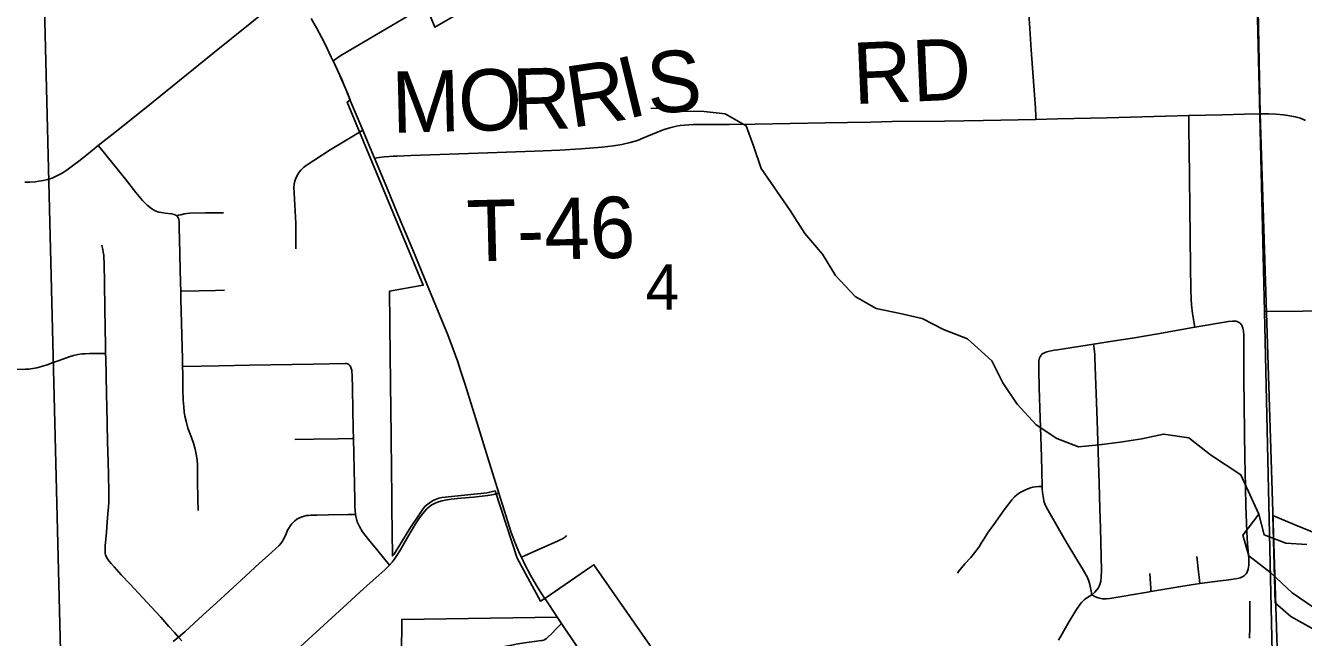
# Model space of a CAD drawing. Extents: x -6.4 to 34, y -4.2 to 22.
# Drawn here: x 5.93 to 7.115, y 14.854 to 15.421 of the extents above; entities that cross this region are included whole.
import ezdxf

# ---------------------------------------------------------------- set-up
doc = ezdxf.new("R2010")
doc.units = 0
for name, color, linetype in [('GM_X_City_Street', 7, 'Continuous'), ('GM_X_Corporation', 7, 'Continuous'), ('GM_X_County_Road', 7, 'Continuous'), ('GM_X_Major_Lake', 7, 'Continuous'), ('GM_X_Minor_River', 7, 'Continuous'), ('GM_X_Section_Text', 7, 'Continuous'), ('GM_X_Township_Road', 7, 'Continuous'), ('GM_X_Township_Road_Text', 7, 'Continuous'), ('GM_X_US_Route', 7, 'Continuous')]:
    doc.layers.add(name, color=color, linetype=linetype)

msp = doc.modelspace()

# ---------------------------------------------------------------- linework, layer by layer
at = {"layer": 'GM_X_City_Street'}
for points in [[(6.1803, 15.214), (6.1803, 15.2376), (6.1787, 15.271), (6.1788, 15.2734), (6.1792, 15.2757), (6.1802, 15.2785), (6.1817, 15.2818), (6.1835, 15.2849), (6.1854, 15.2872), (6.1875, 15.2893), (6.1899, 15.2911), (6.2123, 15.3055), (6.2292, 15.3158), (6.2424, 15.3238)], [(6.0898, 14.9715), (6.0896, 14.9821), (6.0894, 14.9991), (6.0893, 15.0075), (6.0891, 15.0138), (6.0888, 15.0183), (6.0881, 15.0238), (6.0872, 15.0284), (6.0855, 15.0338), (6.0836, 15.039), (6.0804, 15.0478), (6.0786, 15.0542), (6.0776, 15.0588), (6.0769, 15.0628), (6.0765, 15.0676), (6.0761, 15.0737), (6.0758, 15.0835), (6.0755, 15.098), (6.0754, 15.1048), (6.0752, 15.1116), (6.0738, 15.1677), (6.0737, 15.1748), (6.0735, 15.1824), (6.0729, 15.2079), (6.0726, 15.2237), (6.0724, 15.2314), (6.0722, 15.2396), (6.072, 15.2409), (6.0716, 15.2422), (6.071, 15.2433), (6.07, 15.2445), (6.0691, 15.2451), (6.0676, 15.2458), (6.0652, 15.2464), (6.0594, 15.247), (6.0558, 15.2475), (6.0534, 15.248), (6.05, 15.2492), (6.047, 15.2509), (6.0427, 15.2543), (6.0383, 15.2586), (6.032, 15.2662), (6.0226, 15.2785), (5.9989, 15.3076), (5.9973, 15.3095)], [(6.07, 15.2445), (6.0717, 15.245), (6.0739, 15.2455), (6.077, 15.2462), (6.0793, 15.2466), (6.0822, 15.2468), (6.0964, 15.2471), (6.1132, 15.2473)], [(6.0748, 14.8507), (6.0717, 14.8541), (6.0678, 14.8586), (6.0628, 14.8642), (6.0552, 14.8727), (6.051, 14.8772), (6.0384, 14.8908), (6.0267, 14.9034), (6.0185, 14.912), (6.012, 14.9192), (6.0092, 14.9225), (6.0072, 14.9248), (6.0059, 14.9267), (6.005, 14.9284), (6.004, 14.9306), (6.0037, 14.9316), (6.0036, 14.9328), (6.0035, 14.934), (6.0035, 14.9354), (6.0036, 14.9366), (6.0037, 14.939), (6.004, 14.9418), (6.0042, 14.9449), (6.0048, 14.9513), (6.0056, 14.9608), (6.0062, 14.9685), (6.0067, 14.975), (6.0069, 14.9792), (6.007, 14.9844), (6.0069, 14.9885), (6.0066, 15.0044), (6.0063, 15.0166), (6.0059, 15.0353), (6.0053, 15.0677), (6.005, 15.0791), (6.0046, 15.0971), (6.0042, 15.1124), (6.0041, 15.117), (6.004, 15.1257), (6.0037, 15.1396), (6.0027, 15.2014), (6.0025, 15.2048), (6.0023, 15.2079), (6.0019, 15.2108), (6.0015, 15.2132), (6.001, 15.2158), (6.0006, 15.2173)], [(6.0737, 15.1748), (6.0747, 15.1748), (6.0909, 15.175), (6.1059, 15.1754), (6.1143, 15.1755)], [(5.8567, 15.1007), (5.8644, 15.1011), (5.8894, 15.1015), (5.9117, 15.1019), (5.9172, 15.102), (5.9297, 15.1023), (5.9329, 15.1025), (5.9365, 15.103), (5.9403, 15.1037), (5.9445, 15.1049), (5.9498, 15.1066), (5.9554, 15.1085), (5.9611, 15.1105), (5.967, 15.1127), (5.9711, 15.1141), (5.9743, 15.1151), (5.9784, 15.1159), (5.9822, 15.1165), (5.985, 15.1167), (5.989, 15.1169), (5.9939, 15.1169), (6.0024, 15.117), (6.0041, 15.117)], [(6.0754, 15.1048), (6.0761, 15.1048), (6.1094, 15.1055), (6.1376, 15.1061), (6.1967, 15.1072), (6.2261, 15.1077), (6.2271, 15.1077), (6.2283, 15.1075), (6.2291, 15.1071), (6.2301, 15.1062)], [(6.2673, 14.9209), (6.2566, 14.934), (6.2479, 14.9446), (6.2423, 14.9519), (6.2395, 14.9566), (6.2374, 14.961), (6.2362, 14.965), (6.2358, 14.9678), (6.2353, 14.9715), (6.2352, 14.9751), (6.2351, 14.9814), (6.2339, 15.0382), (6.2337, 15.0469), (6.233, 15.084), (6.2326, 15.0973), (6.2324, 15.0995), (6.2322, 15.1014), (6.2318, 15.1031), (6.2312, 15.1048), (6.2301, 15.1062)], [(6.1794, 15.0374), (6.197, 15.0376), (6.2196, 15.038), (6.2326, 15.0382), (6.2339, 15.0382)], [(6.1809, 14.8422), (6.2245, 14.8819), (6.2435, 14.8992), (6.2628, 14.9167), (6.2673, 14.9209), (6.2698, 14.9237), (6.2716, 14.9262), (6.2739, 14.9297), (6.2767, 14.9343), (6.2804, 14.9407), (6.2864, 14.9509), (6.292, 14.96), (6.295, 14.9646), (6.2982, 14.9686), (6.3019, 14.9732), (6.3039, 14.975), (6.3065, 14.9769), (6.3095, 14.9784), (6.3126, 14.9795), (6.3161, 14.9805), (6.3187, 14.9811), (6.3245, 14.982), (6.3333, 14.9829), (6.3451, 14.984), (6.3585, 14.9854), (6.362, 14.9859), (6.3652, 14.9866), (6.3685, 14.9876)], [(6.0668, 14.8501), (6.0717, 14.8541), (6.0774, 14.8592), (6.0942, 14.8745), (6.1068, 14.886), (6.1298, 14.907), (6.1468, 14.9226), (6.1549, 14.9298), (6.165, 14.9392), (6.1665, 14.9409), (6.1681, 14.9432), (6.1691, 14.9449), (6.1702, 14.9472), (6.1714, 14.95), (6.1728, 14.9532), (6.174, 14.9553), (6.1754, 14.9577), (6.1768, 14.9593), (6.1791, 14.9617), (6.1813, 14.9634), (6.1839, 14.9648), (6.1863, 14.9657), (6.1882, 14.9663), (6.1903, 14.9668), (6.1924, 14.967), (6.1943, 14.9671), (6.1998, 14.9672), (6.2106, 14.9674), (6.2289, 14.9677), (6.2358, 14.9678)]]:
    msp.add_lwpolyline(points, dxfattribs=at)
at = {"layer": 'GM_X_Corporation'}
for points in [[(7.1124, 14.1), (8.9, 14.1), (8.9, 15.9356), (8.6815, 15.9311), (7.2926, 15.9044), (7.2702, 15.904), (7.0636, 15.9014), (7.0744, 15.3393), (7.0897, 14.8536), (7.0948, 14.7153), (7.0983, 14.5939), (7.1017, 14.4646)], [(8.0507, 15.9235), (8.0705, 15.1646), (7.0784, 15.1559), (7.0606, 15.9074)], [(5.9608, 15.8844), (7.0606, 15.9074), (7.0784, 15.1559), (7.0887, 14.7028), (5.9664, 14.6804), (5.9363, 15.8839)], [(4.9247, 15.8623), (5.9363, 15.8839), (5.9664, 14.6804), (5.9632, 14.6804), (4.8443, 14.6554), (4.8285, 15.2133), (4.8102, 15.8601)], [(7.0784, 15.1559), (8.0705, 15.1646), (8.0954, 14.1535), (7.1021, 14.1428), (7.0887, 14.7028)]]:
    msp.add_lwpolyline(points, close=True, dxfattribs=at)
for points in [[(2.1, 14.1), (7.1124, 14.1), (7.1017, 14.4646), (7.0983, 14.5939), (7.0948, 14.7153), (7.0897, 14.8536), (7.0744, 15.3393), (7.0636, 15.9014), (6.8667, 15.898), (6.7596, 15.897), (6.5599, 15.8933), (5.7185, 15.8776)], [(6.3051, 15.4291), (6.3093, 15.4192), (6.3633, 15.4508)], [(6.5177, 14.8335), (6.4709, 14.9007), (6.4567, 14.9213), (6.4538, 14.9193), (6.435, 14.9065), (6.4112, 14.8901), (6.4072, 14.8876), (6.3856, 14.9273), (6.3651, 14.9897), (6.3577, 14.988), (6.3157, 14.9835), (6.3129, 14.9828), (6.31, 14.9818), (6.3078, 14.9809), (6.3052, 14.9793), (6.3027, 14.9775), (6.3004, 14.9754), (6.2981, 14.9727), (6.2968, 14.9709), (6.2862, 14.9548), (6.2724, 14.9327), (6.2715, 14.9312), (6.27, 14.9295), (6.2695, 14.9739), (6.2693, 14.989), (6.2693, 14.9896), (6.2692, 15.0042), (6.2692, 15.0064), (6.2691, 15.0121), (6.269, 15.0169), (6.269, 15.0193), (6.269, 15.0216), (6.2689, 15.0264), (6.2689, 15.0311), (6.2688, 15.0345), (6.2688, 15.0358), (6.2688, 15.0406), (6.2687, 15.0453), (6.2687, 15.0498), (6.2687, 15.0501), (6.2686, 15.0548), (6.2686, 15.0603), (6.2685, 15.0643), (6.2685, 15.065), (6.2685, 15.0691), (6.2684, 15.0738), (6.2683, 15.0801), (6.2682, 15.0953), (6.268, 15.1104), (6.268, 15.1125), (6.2676, 15.1457), (6.2673, 15.1748), (6.2946, 15.1797), (6.2985, 15.1802), (6.228, 15.3499), (6.2307, 15.352), (6.2283, 15.3579), (6.2229, 15.3706), (6.2187, 15.38), (6.215, 15.388), (6.2221, 15.393), (6.3008, 15.4392)], [(7.1679, 14.9332), (7.1059, 14.9586), (7.0862, 14.9668), (7.0884, 14.8858), (7.0887, 14.8856), (7.1027, 14.8733), (7.1366, 14.8546)], [(6.2769, 14.6708), (6.2786, 14.8707), (6.4227, 14.8728), (6.4264, 14.8673), (6.4403, 14.8468)]]:
    msp.add_lwpolyline(points, dxfattribs=at)
at = {"layer": 'GM_X_County_Road'}
for points in [[(6.1238, 15.4112), (6.1253, 15.4125), (6.1397, 15.424), (6.1605, 15.4407), (6.1687, 15.4471), (6.178, 15.454)], [(5.9293, 15.2755), (5.9338, 15.2757), (5.9389, 15.2761), (5.9422, 15.2765), (5.9465, 15.2772), (5.9501, 15.2781), (5.9544, 15.2795), (5.9588, 15.2814), (5.9631, 15.2837), (5.9672, 15.2862), (5.971, 15.2889), (5.9747, 15.2917), (5.9791, 15.295), (5.9881, 15.3022), (5.9973, 15.3095), (6.0168, 15.325), (6.0483, 15.3502), (6.0727, 15.3699), (6.1035, 15.3947), (6.1207, 15.4087), (6.1238, 15.4112)], [(7.0746, 15.3388), (7.082, 15.3388), (7.0889, 15.3386), (7.096, 15.338), (7.1018, 15.3372), (7.1069, 15.3362), (7.1118, 15.3348), (7.1164, 15.3329)]]:
    msp.add_lwpolyline(points, dxfattribs=at)
at = {"layer": 'GM_X_Major_Lake'}
msp.add_lwpolyline([(7.1178, 14.9399), (7.0981, 14.9412), (7.0781, 14.9489), (7.0733, 14.9682), (7.0584, 14.9486), (7.0639, 14.9296), (7.0843, 14.9139), (7.1042, 14.8952), (7.1246, 14.8814)], dxfattribs=at)
at = {"layer": 'GM_X_Minor_River'}
msp.add_lwpolyline([(7.0733, 14.9682), (7.0566, 15.0047), (7.0285, 15.0231), (7.0082, 15.0388), (6.9847, 15.0423), (6.9646, 15.0378), (6.9446, 15.0349), (6.9252, 15.0323), (6.9059, 15.0305), (6.8859, 15.0382), (6.8667, 15.0508), (6.849, 15.0699), (6.8358, 15.0897), (6.8257, 15.1102), (6.8032, 15.1305), (6.7809, 15.1393), (6.7609, 15.1493), (6.7408, 15.1539), (6.7185, 15.1586), (6.6989, 15.1697), (6.6808, 15.1891), (6.6685, 15.2089), (6.6523, 15.228), (6.6388, 15.2493), (6.6118, 15.2882), (6.6051, 15.3083), (6.598, 15.3277), (6.5784, 15.3388), (6.5591, 15.3412), (6.5398, 15.3413), (6.5171, 15.344), (6.5095, 15.3441)], dxfattribs=at)
at = {"layer": 'GM_X_Township_Road'}
for points in [[(6.8663, 15.3338), (6.8663, 15.3365), (6.866, 15.3442), (6.8653, 15.3566), (6.8622, 15.3982), (6.8609, 15.418), (6.8589, 15.4446)], [(6.2533, 15.298), (6.2577, 15.2985), (6.2623, 15.299), (6.2668, 15.2994), (6.2707, 15.2996), (6.2745, 15.2998), (6.2869, 15.3002), (6.3583, 15.3028), (6.4018, 15.3043), (6.4098, 15.3046), (6.4253, 15.3054), (6.4445, 15.3065), (6.4643, 15.308), (6.4748, 15.3093), (6.4827, 15.3106), (6.4905, 15.3124), (6.497, 15.3143), (6.5022, 15.3163), (6.5148, 15.3216), (6.5218, 15.3243), (6.5272, 15.3259), (6.5333, 15.3274), (6.5366, 15.328), (6.5408, 15.3285), (6.5489, 15.329), (6.5607, 15.3292), (6.5825, 15.3292), (6.6061, 15.3294), (6.6712, 15.3306), (6.6917, 15.3308), (6.7134, 15.3312), (6.7332, 15.3317), (6.7817, 15.3322), (6.7997, 15.3325), (6.8177, 15.3327), (6.8663, 15.3338), (6.8866, 15.3342), (6.9326, 15.3353), (7.0083, 15.3375), (7.0392, 15.3381), (7.06, 15.3385), (7.0746, 15.3388)], [(7.0139, 15.1412), (7.013, 15.1466), (7.0117, 15.154), (7.0108, 15.162), (7.0104, 15.1674), (7.01, 15.1766), (7.0097, 15.1971), (7.0094, 15.2251), (7.0087, 15.3071), (7.0084, 15.3232), (7.0083, 15.3375)], [(6.8702, 15.1135), (6.8706, 15.1143), (6.8711, 15.1152), (6.8716, 15.1158), (6.8722, 15.1165), (6.873, 15.117), (6.8739, 15.1174), (6.875, 15.1179), (6.8765, 15.1184), (6.8779, 15.1188), (6.8834, 15.1199), (6.8865, 15.1204), (6.92, 15.1257), (6.9395, 15.1287), (6.9579, 15.1316), (6.9794, 15.1351), (7.0139, 15.1412), (7.045, 15.1467), (7.0487, 15.147), (7.0499, 15.147), (7.0512, 15.1469), (7.052, 15.1468), (7.0531, 15.1466)], [(7.0624, 14.9146), (7.063, 14.9161), (7.0634, 14.9173), (7.0637, 14.9187), (7.0639, 14.9211), (7.064, 14.9225), (7.064, 14.927), (7.0628, 14.9406), (7.0619, 14.9518), (7.0611, 14.976), (7.0604, 15.0083), (7.0603, 15.0195), (7.0592, 15.0941), (7.0593, 15.1139), (7.0592, 15.1183), (7.0592, 15.1214), (7.0592, 15.1308), (7.0591, 15.134), (7.0589, 15.1377), (7.0587, 15.139), (7.0584, 15.1403), (7.0578, 15.1422), (7.0573, 15.1431), (7.0567, 15.1439), (7.0557, 15.1449), (7.0548, 15.1456), (7.0539, 15.1461), (7.0531, 15.1466)], [(6.9183, 14.8935), (6.9211, 14.896), (6.923, 14.898), (6.9243, 14.8996), (6.9252, 14.9013), (6.9259, 14.903), (6.9266, 14.906), (6.927, 14.9097), (6.9272, 14.9159), (6.9269, 14.9289), (6.9263, 14.9551), (6.9258, 14.9731), (6.9252, 14.9967), (6.9233, 15.055), (6.9211, 15.1128), (6.921, 15.1156), (6.9208, 15.1189), (6.9202, 15.1236), (6.92, 15.1257)], [(6.9183, 14.8935), (6.9174, 14.8982), (6.9165, 14.903), (6.9156, 14.906), (6.9142, 14.9094), (6.9105, 14.9159), (6.8955, 14.9409), (6.8911, 14.9485), (6.8812, 14.9657), (6.879, 14.9694), (6.876, 14.9749), (6.8748, 14.9777), (6.8743, 14.9791), (6.8738, 14.9807), (6.8735, 14.9825), (6.8729, 14.9862), (6.8724, 14.9912), (6.8724, 14.9936), (6.8721, 15.0079), (6.8716, 15.021), (6.8714, 15.0303), (6.871, 15.0402), (6.8704, 15.057), (6.8694, 15.0855), (6.8691, 15.1011), (6.8693, 15.1079), (6.8693, 15.11), (6.8695, 15.1114), (6.8698, 15.1126), (6.8702, 15.1135)], [(6.7937, 14.9135), (6.7948, 14.9149), (6.8007, 14.9221), (6.8062, 14.9281), (6.8097, 14.9323), (6.8118, 14.9352), (6.8138, 14.938), (6.8158, 14.9413), (6.8188, 14.946), (6.8217, 14.9504), (6.8276, 14.9585), (6.8372, 14.9722), (6.8413, 14.9778), (6.8441, 14.9815), (6.8465, 14.9841), (6.8489, 14.9861), (6.8513, 14.9878), (6.8536, 14.9892), (6.8561, 14.9905), (6.8589, 14.9917), (6.8614, 14.9926), (6.8637, 14.9931), (6.8662, 14.9934), (6.869, 14.9936), (6.8724, 14.9936)], [(6.3895, 14.9282), (6.3958, 14.931), (6.4104, 14.9374), (6.4229, 14.9431), (6.4262, 14.9445), (6.4276, 14.9453), (6.4287, 14.9459), (6.4293, 14.9463), (6.4299, 14.9467), (6.4307, 14.9474), (6.4314, 14.9485)], [(7.0185, 14.9038), (7.0177, 14.9098), (7.0172, 14.9146), (7.0158, 14.9288)], [(6.9183, 14.8935), (6.9218, 14.8917), (6.9243, 14.8906), (6.9267, 14.8899), (6.9282, 14.8897), (6.9298, 14.8896), (6.9319, 14.8898), (6.935, 14.8901), (6.97, 14.8959), (6.9731, 14.8965), (6.9989, 14.9009), (7.0104, 14.9027), (7.0185, 14.9038), (7.0303, 14.9054), (7.0375, 14.9063), (7.0452, 14.9072), (7.0514, 14.9081), (7.0535, 14.9086), (7.0557, 14.9092), (7.0571, 14.9097), (7.0581, 14.9102), (7.0598, 14.9113), (7.0606, 14.912), (7.0613, 14.9128), (7.0619, 14.9138), (7.0624, 14.9146)], [(6.9731, 14.8965), (6.973, 14.8994), (6.9722, 14.9133)], [(6.8875, 14.8515), (6.8908, 14.8574), (6.8965, 14.8671), (6.9035, 14.8788), (6.9076, 14.8849), (6.909, 14.8866), (6.9105, 14.8882), (6.9113, 14.8889), (6.9129, 14.8901), (6.9183, 14.8935)], [(7.0646, 14.8533), (7.0649, 14.8636), (7.0647, 14.8875)], [(6.3599, 14.8404), (6.3604, 14.841), (6.3609, 14.8415), (6.3615, 14.8419), (6.3622, 14.8422), (6.3646, 14.8432), (6.372, 14.8451), (6.3806, 14.8469), (6.3848, 14.8477), (6.3924, 14.8488), (6.4035, 14.8504), (6.4083, 14.8511), (6.4092, 14.8512), (6.4104, 14.8515), (6.4111, 14.8519), (6.4117, 14.8522), (6.4123, 14.8526), (6.4129, 14.8531), (6.4141, 14.8541), (6.4177, 14.8577), (6.4221, 14.8623), (6.4266, 14.8668)]]:
    msp.add_lwpolyline(points, dxfattribs=at)
at = {"layer": 'GM_X_US_Route'}
for points in [[(6.1946, 15.4273), (6.1995, 15.4186), (6.2041, 15.4101), (6.2078, 15.4029), (6.2133, 15.3915), (6.2148, 15.3883)], [(6.2148, 15.3883), (6.2152, 15.3875), (6.2189, 15.3794), (6.2231, 15.3701), (6.2285, 15.3574), (6.2309, 15.3514)], [(6.2309, 15.3514), (6.2354, 15.3406), (6.2424, 15.3238), (6.2452, 15.3171), (6.2533, 15.298), (6.2648, 15.2707), (6.2751, 15.2458), (6.2894, 15.2113), (6.3022, 15.1804), (6.3139, 15.1522), (6.3212, 15.1341), (6.3264, 15.121), (6.3306, 15.1093), (6.3335, 15.1003), (6.3372, 15.0891), (6.3399, 15.0802), (6.343, 15.0702), (6.3472, 15.0564), (6.3584, 15.0202), (6.3685, 14.9876)], [(6.3685, 14.9876), (6.3738, 14.9708), (6.3801, 14.9511), (6.3841, 14.9407), (6.3882, 14.931), (6.3895, 14.9282), (6.3929, 14.921), (6.3978, 14.9117), (6.4034, 14.9021), (6.4074, 14.8957), (6.4109, 14.8903)], [(6.4109, 14.8903), (6.4114, 14.8896), (6.4229, 14.8723)], [(6.4229, 14.8723), (6.4266, 14.8668), (6.4405, 14.8462), (6.4514, 14.8302), (6.4628, 14.8139)]]:
    msp.add_lwpolyline(points, dxfattribs=at)

# ---------------------------------------------------------------- texts
at = {"layer": 'GM_X_Section_Text'}
msp.add_text('4', height=0.0419, rotation=0, dxfattribs=at).set_placement((6.5046, 15.1577))
at = {"layer": 'GM_X_Township_Road_Text'}
for s, height, rotation, p in [('RD', 0.05682, 2.4677, (6.6978, 15.3479)), ('I', 0.0568, 13.6819, (6.4874, 15.3339)), ('S', 0.0568, 3.7041, (6.5075, 15.339)), ('M', 0.0568, 1.4016, (6.2699, 15.3213)), ('O', 0.0568, 1.4028, (6.3315, 15.3228)), ('R', 0.0568, 1.496, (6.3816, 15.324)), ('R', 0.0568, 8.5309, (6.4358, 15.3259)), ('T-46', 0.05682, 1.415, (6.3395, 15.202))]:
    msp.add_text(s, height=height, rotation=rotation, dxfattribs=at).set_placement(p)

doc.saveas('drawing.dxf')
